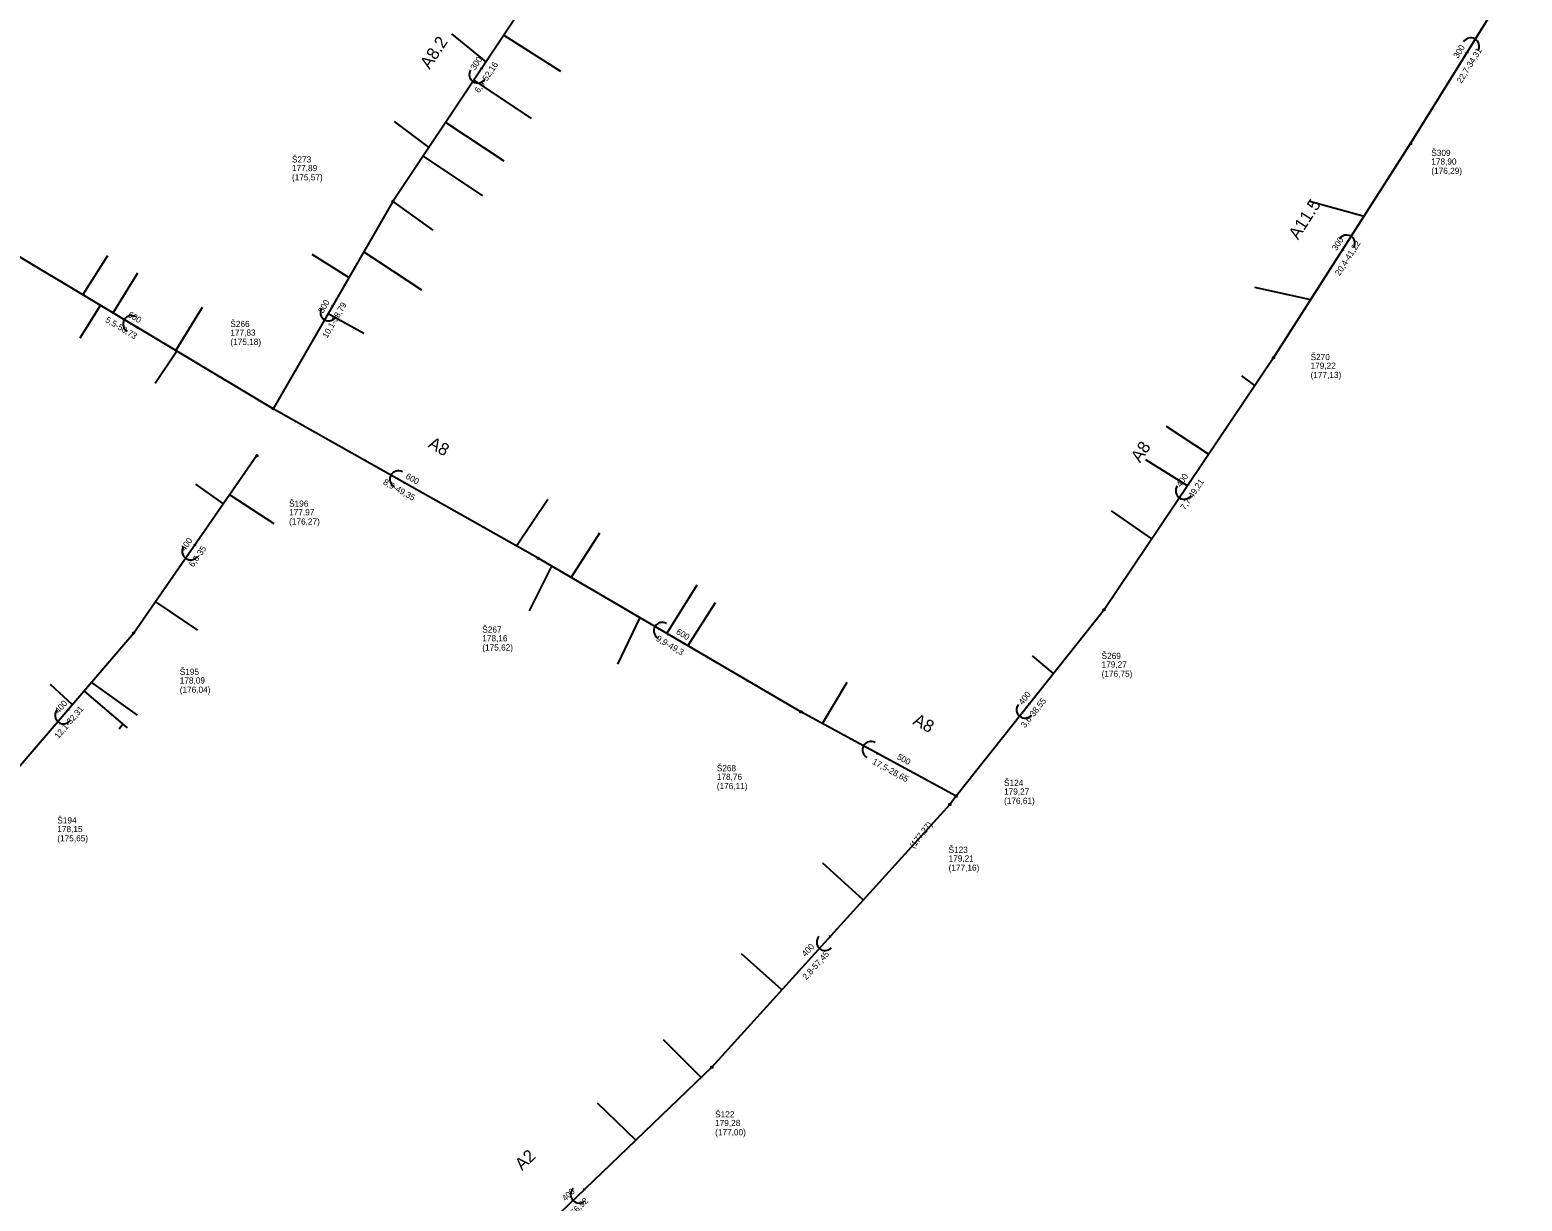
# Model space of a CAD drawing. Extents: x -548529 to -543591, y -1201432 to -1192608.
# Drawn here: x -544134.8 to -543892.9, y -1193181.6 to -1192991.9 of the extents above; entities that cross this region are included whole.
import ezdxf

# ---------------------------------------------------------------- set-up
doc = ezdxf.new("R2010")
doc.units = 0
for name, color, linetype in [('C3D_Bod-Značky', 7, 'Continuous'), ('C3D_Koridor', 7, 'Continuous'), ('C3D_Křižovatka', 7, 'Continuous'), ('C3D_Netisknutelná', 7, 'Continuous'), ('C3D_PP-zobrazeni v PR', 7, 'Continuous'), ('C3D_PR-Popisek', 7, 'Continuous'), ('C3D_SPR-Popisek', 7, 'Continuous'), ('C3D_Tlakove_potrubi_Popis', 7, 'Continuous'), ('C3D_ZPR-Formaty', 7, 'Continuous')]:
    doc.layers.add(name, color=color, linetype=linetype)

# ---------------------------------------------------------------- blocks, each defined once
blk = doc.blocks.new('100')
at = {"layer": 'Defpoints'}
blk.add_circle((0, 0), 0.127, dxfattribs=at)
blk = doc.blocks.new('91')
at = {"layer": 'Defpoints'}
blk.add_lwpolyline([(0.08, 0.14), (0.19, 0), (0.08, -0.14)], dxfattribs=at)
blk.add_arc((1.37, 0), 1.37, 270, 90, dxfattribs=at)

msp = doc.modelspace()

# ---------------------------------------------------------------- linework, layer by layer
at = {"layer": 'C3D_Bod-Značky'}
for points in [[(-544046.944, -1192976.265), (-544075.903, -1193019.652)], [(-543910.943, -1193010.277), (-543892.871, -1192981.108)], [(-543933.179, -1193044.981), (-543910.943, -1193010.277)], [(-544075.903, -1193019.652), (-544095.329, -1193053.232)], [(-544095.329, -1193053.232), (-544138.857, -1193027.179)], [(-543933.179, -1193044.981), (-543960.647, -1193085.811)], [(-544052.344, -1193077.465), (-544095.329, -1193053.232)], [(-544097.957, -1193060.837), (-544117.914, -1193089.586)], [(-544009.782, -1193102.338), (-544052.344, -1193077.465)], [(-543960.647, -1193085.811), (-543984.602, -1193116.01)], [(-544117.914, -1193089.586), (-544138.909, -1193114.142)], [(-543984.602, -1193116.01), (-544009.782, -1193102.338)], [(-543985.64, -1193117.349), (-544024.223, -1193159.914)], [(-543984.602, -1193116.01), (-543985.64, -1193117.349)], [(-544024.223, -1193159.914), (-544065.286, -1193199.332)]]:
    msp.add_lwpolyline(points, dxfattribs=at)
at = {"layer": 'C3D_Koridor'}
for points in [[(-544060.799, -1192997.023), (-544066.373, -1192992.51)], [(-544057.91, -1192992.694), (-544048.721, -1192998.547)], [(-544062.807, -1193000.031), (-544053.486, -1193006.2)], [(-544070.059, -1193010.896), (-544075.662, -1193006.712)], [(-544067.357, -1193006.847), (-544057.912, -1193013.085)], [(-544071.006, -1193012.316), (-544061.377, -1193018.74)], [(-544075.903, -1193019.652), (-544069.442, -1193024.291)], [(-543918.499, -1193022.07), (-543927.291, -1193019.646)], [(-544080.626, -1193027.816), (-544071.293, -1193033.995)], [(-544126.169, -1193034.773), (-544122.133, -1193028.394)], [(-544083.038, -1193031.985), (-544089.025, -1193028.242)], [(-544121.24, -1193037.723), (-544117.248, -1193031.223)], [(-543927.147, -1193035.568), (-543936.211, -1193033.602)], [(-544123.327, -1193036.474), (-544126.654, -1193041.81)], [(-544111.101, -1193043.792), (-544106.788, -1193036.791)], [(-544086.392, -1193037.783), (-544080.634, -1193040.99)], [(-544110.929, -1193043.896), (-544114.474, -1193049.152)], [(-543936.204, -1193049.478), (-543938.308, -1193047.89)], [(-543943.69, -1193060.605), (-543950.533, -1193056.137)], [(-543947.134, -1193065.724), (-543953.894, -1193061.491)], [(-544103.391, -1193068.666), (-544107.854, -1193065.445)], [(-544102.348, -1193067.162), (-544095.194, -1193071.836)], [(-544055.885, -1193075.469), (-544050.796, -1193067.913)], [(-543952.913, -1193074.315), (-543959.425, -1193069.759)], [(-544047.013, -1193080.58), (-544042.376, -1193073.357)], [(-544050.203, -1193078.717), (-544053.807, -1193085.958)], [(-544031.521, -1193089.634), (-544026.577, -1193081.743)], [(-544114.386, -1193084.504), (-544107.566, -1193089.127)], [(-544028.098, -1193091.634), (-544023.598, -1193084.62)], [(-544035.879, -1193087.087), (-544039.527, -1193094.638)], [(-543968.838, -1193096.137), (-543972.253, -1193093.281)], [(-544127.87, -1193101.23), (-544131.431, -1193097.897)], [(-544124.744, -1193097.574), (-544117.364, -1193102.889)], [(-544006.257, -1193104.252), (-544002.256, -1193097.538)], [(-544125.979, -1193099.018), (-544118.982, -1193104.949)], [(-544119.713, -1193104.33), (-544120.309, -1193105.147)], [(-543999.663, -1193132.819), (-544006.241, -1193126.861)], [(-544012.86, -1193147.378), (-544019.415, -1193141.561)], [(-544025.962, -1193161.583), (-544032.05, -1193155.5)], [(-544036.537, -1193171.735), (-544042.753, -1193165.739)]]:
    msp.add_lwpolyline(points, dxfattribs=at)

# ---------------------------------------------------------------- block references
at = {"layer": 'C3D_PP-zobrazeni v PR'}
for p, xscale, yscale, rotation in [((-543910.943, -1193010.277), 0.9999999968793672, 0.9999999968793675, -122.00000027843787), ((-544075.903, -1193019.652), 1.0000000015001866, 1.0000000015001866, -120.99999982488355), ((-543933.179, -1193044.981), 0.9999999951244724, 0.9999999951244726, -123.00000127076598), ((-544095.329, -1193053.232), 0.9999999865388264, 0.9999999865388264, 149.99999955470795), ((-544097.957, -1193060.837), 0.9999999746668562, 0.999999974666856, 55.999999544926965), ((-544052.344, -1193077.465), 1.0037042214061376, 1.0037042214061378, 150.62079160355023), ((-543960.647, -1193085.811), 1.000000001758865, 1.000000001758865, -125.99999933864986), ((-544117.914, -1193089.586), 0.9999999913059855, 0.9999999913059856, -127.00000193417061), ((-544009.782, -1193102.338), 1.0037042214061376, 1.0037042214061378, 150.62079160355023), ((-543985.64, -1193117.349), 1.000000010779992, 1.0000000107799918, -128.99999891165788), ((-543984.602, -1193116.01), 1.0000000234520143, 1.0000000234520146, -78.0000006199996), ((-544024.223, -1193159.914), 1.0000000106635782, 1.0000000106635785, -134.00000165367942)]:
    msp.add_blockref('100', p, dxfattribs=dict(at, xscale=xscale, yscale=yscale, rotation=rotation))
at = {"layer": 'C3D_SPR-Popisek'}
for p, xscale, yscale, rotation in [((-543901.907, -1192995.692), 1.0000000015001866, 1.0000000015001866, 59.00000017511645), ((-544061.424, -1192997.958), 0.9999999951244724, 0.9999999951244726, -123.00000127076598), ((-543922.061, -1193027.629), 0.9999999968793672, 0.9999999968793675, 57.99999972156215), ((-544085.616, -1193036.442), 0.9999999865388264, 0.9999999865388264, -120.00000044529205), ((-544117.093, -1193040.206), 0.9999999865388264, 0.9999999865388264, 149.99999955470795), ((-544073.836, -1193065.348), 1.0037042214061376, 1.0037042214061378, 150.62079160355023), ((-543946.913, -1193065.396), 0.9999999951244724, 0.9999999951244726, -123.00000127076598), ((-544107.936, -1193075.212), 0.9999999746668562, 0.999999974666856, -124.00000045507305), ((-544031.063, -1193089.902), 0.9999999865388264, 0.9999999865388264, 149.99999955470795), ((-543972.624, -1193100.91), 1.000000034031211, 1.0000000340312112, -128.00000040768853), ((-544128.411, -1193101.864), 1.0000000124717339, 1.0000000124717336, -130.0000013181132), ((-543997.192, -1193109.174), 1.0072562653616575, 1.0072562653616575, 151.23333487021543), ((-544004.932, -1193138.632), 1.0000000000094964, 1.0000000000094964, -132.0000013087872), ((-544044.754, -1193179.623), 1.0000000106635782, 1.0000000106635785, -135.99999834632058)]:
    msp.add_blockref('91', p, dxfattribs=dict(at, xscale=xscale, yscale=yscale, rotation=rotation))

# ---------------------------------------------------------------- texts
at = {"layer": 'C3D_Křižovatka'}
for s, p in [('Š309', (-543907.593, -1193012.287)), ('Š273', (-544092.273, -1193013.342)), ('Š266', (-544102.259, -1193040.002)), ('Š270', (-543927.169, -1193045.361)), ('Š196', (-544092.737, -1193069.107)), ('Š267', (-544061.424, -1193089.515)), ('Š269', (-543961.037, -1193093.771)), ('Š195', (-544110.464, -1193096.356)), ('Š268', (-544023.412, -1193111.968)), ('Š124', (-543976.852, -1193114.35)), ('Š194', (-544130.309, -1193120.432)), ('Š123', (-543985.84, -1193125.199)), ('Š122', (-544023.683, -1193168.054))]:
    msp.add_text(s, height=1, dxfattribs=at).set_placement(p)
at = {"layer": 'C3D_Netisknutelná'}
for s, rotation, p in [('A8.2', 56.28, (-544069.984, -1192998.348)), ('A11.5', 57.35, (-543929.196, -1193025.975)), ('A8', 330.59, (-544070.358, -1193059.392)), ('A8', 56.07, (-543954.805, -1193062.103)), ('A8', 331.5, (-543991.779, -1193104.265)), ('A2', 43.83, (-544054.971, -1193176.767))]:
    msp.add_text(s, height=2, rotation=rotation, dxfattribs=at).set_placement(p)
at = {"layer": 'C3D_PR-Popisek'}
for s, rotation, p in [('300', 56.28, (-544062.608, -1192998.463)), ('300', 58.22, (-543903.27, -1192996.558)), ('300', 57.35, (-543922.95, -1193027.72)), ('600', 329.1, (-544118.961, -1193038.269)), ('300', 59.95, (-544087.243, -1193037.862)), ('600', 330.59, (-544073.961, -1193064.468)), ('400', 56.07, (-543948.184, -1193066.038)), ('400', 55.23, (-544109.617, -1193076.403)), ('600', 329.7, (-544030.109, -1193089.651)), ('400', 49.47, (-544130.051, -1193102.709)), ('400', 51.58, (-543973.816, -1193101.289)), ('500', 331.5, (-543994.307, -1193109.943)), ('400', 47.81, (-544009.018, -1193142.094)), ('400', 43.83, (-544047.932, -1193181.701))]:
    msp.add_text(s, height=1, rotation=rotation, dxfattribs=at).set_placement(p)
at = {"layer": 'C3D_Tlakove_potrubi_Popis'}
for s, p in [('178,90 ', (-543907.593, -1193013.687)), ('(175,57)', (-544092.273, -1193016.242)), ('177,89 ', (-544092.273, -1193014.742)), ('(176,29)', (-543907.593, -1193015.187)), ('(175,18)', (-544102.259, -1193042.902)), ('177,83 ', (-544102.259, -1193041.402)), ('(177,13)', (-543927.169, -1193048.261)), ('179,22 ', (-543927.169, -1193046.761)), ('(176,27)', (-544092.737, -1193072.007)), ('177,97 ', (-544092.737, -1193070.507)), ('178,16 ', (-544061.424, -1193090.915)), ('(175,62)', (-544061.424, -1193092.415)), ('(176,75)', (-543961.037, -1193096.671)), ('179,27 ', (-543961.037, -1193095.171)), ('178,09 ', (-544110.464, -1193097.756)), ('(176,04)', (-544110.464, -1193099.256)), ('178,76 ', (-544023.412, -1193113.368)), ('(176,11)', (-544023.412, -1193114.868)), ('179,27 ', (-543976.852, -1193115.75)), ('(176,61)', (-543976.852, -1193117.25)), ('(175,65)', (-544130.309, -1193123.332)), ('178,15 ', (-544130.309, -1193121.832)), ('(177,16)', (-543985.84, -1193128.099)), ('179,21 ', (-543985.84, -1193126.599)), ('(177,00)', (-544023.683, -1193170.954)), ('179,28 ', (-544023.683, -1193169.454))]:
    msp.add_text(s, height=1, dxfattribs=at).set_placement(p)
at = {"layer": 'C3D_ZPR-Formaty'}
for s, rotation, p in [('22,7-34,31', 58.22, (-543902.709, -1193000.603)), ('6,9-52,16', 56.28, (-544061.942, -1193002.156)), ('20,4-41,22', 57.35, (-543922.46, -1193031.777)), ('10,1-38,79', 59.95, (-544086.569, -1193041.89)), ('5,5-50,73', 329.1, (-544122.616, -1193039.114)), ('8,9-49,35', 330.59, (-544077.59, -1193065.412)), ('7,7-49,21', 56.07, (-543947.54, -1193069.73)), ('6,6-35', 55.23, (-544108.247, -1193079)), ('9,9-49,3', 329.7, (-544033.358, -1193090.755)), ('3,6-38,55', 51.58, (-543973.457, -1193105.025)), ('12,1-32,31', 49.47, (-544130.124, -1193106.783)), ('17,5-28,65', 331.5, (-543998.313, -1193110.73)), ('  (177,27)   ', 52.22, (-543991.928, -1193125.135)), ('2,8-57,45', 47.81, (-544008.904, -1193145.845)), ('4-56,92', 43.83, (-544047.431, -1193184.817))]:
    msp.add_text(s, height=1, rotation=rotation, dxfattribs=at).set_placement(p)

doc.saveas('drawing.dxf')
